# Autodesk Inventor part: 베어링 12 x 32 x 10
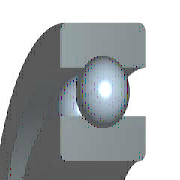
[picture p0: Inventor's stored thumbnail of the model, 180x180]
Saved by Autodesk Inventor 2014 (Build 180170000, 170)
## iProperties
IsCustomPart: 1
Created: 2012-02
Part Number: 베어링 12 x 32 x 10
Material: 강철, 연강
Description: 깊은 그루브 볼 베어링
Document SubType Name: Modeling
Standard: KS B 2023
Designer: test
Standards Organization: KS
Language: ko-KR
Size Designation: 6201 - 12 x 32 x 10
Categories: <MemberInstance><Categories><Category DisplayName="샤프트 부품" InternalName="7f7aeb1f-a693-4053-b835-cee3144e0d98" Mnemonic="SHFT"><Category DisplayName="베어링" Inter
Density: 1 g/cm^3
Appearance: Yellow
Author: test
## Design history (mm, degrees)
sketch "스케치" dims "d0" = 5.2 (= -0.26 x WD + 0.26 x BD)
  geometry: L1 (2.4, 11)-(7.6, 11); L2 (5, 11)-(5, 8.4); L3 (5, 11)-(5, 13.6); L4 (3.068, 9.26)-(0, 9.26); L5 (0, 6)-(10, 6); L6 (3.068, 12.74)-(0, 12.74); L7 (0, 16)-(10, 16); L8 (10, 6)-(10, 9.26); L9 (6.932, 9.26)-(10, 9.26); L10 (6.932, 12.74)-(10, 12.74); L11 (10, 16)-(10, 12.74); L12 (-1.4, 0)-(8.4, 0) reference; L13 (0, -0.3)-(0, 5.3) reference
  constraints: 22 end point, 4 point on line, 2 collinear, 2 perpendicular, 2 symmetric about line, 1 midpoint, 1 parallel, 14 other
  dimensions: "d9" = 12 diameter of L5 L12 (= WD); "d11" = 32 diameter of L7 L12 (= BD); "d12" = 10 distance between parallel lines of L8 L13 (= KB); "d13" = 18.52 diameter of L9 L12 (= 0.326 x BD + 0.674 x WD)
revolve "본체" stored, may be unused: angle "d6" = 90 deg
revolve "볼" stored, may be unused: angle "d7" = 90 deg
pattern_circular "IDS_ARRAYBALL[SIMPL:T]" dims angle "d3" = 360 deg
body "Solid1"
fillet "모깎기1" dims "d1" = 0.6 (= KRS)
other parameters: "WD" = 12 [user parameter; used in 5 equation terms], "BD" = 32 [user parameter; used in 5 equation terms], "KB" = 10 [user parameter; used in 1 equation term], "KRS" = 0.6 [user parameter; used in 1 equation term], "d4" = 0, "d5" = 0, "d8" = 0, "d14" = 0, "d15" = 0, "BBA" = 0 [user parameter], "BC0" = 3100000 [user parameter], "BC" = 6890000 [user parameter], "BR" = 16 (= 0.5 x BD) [user parameter], "WR" = 6 (= 0.5 x WD) [user parameter]
